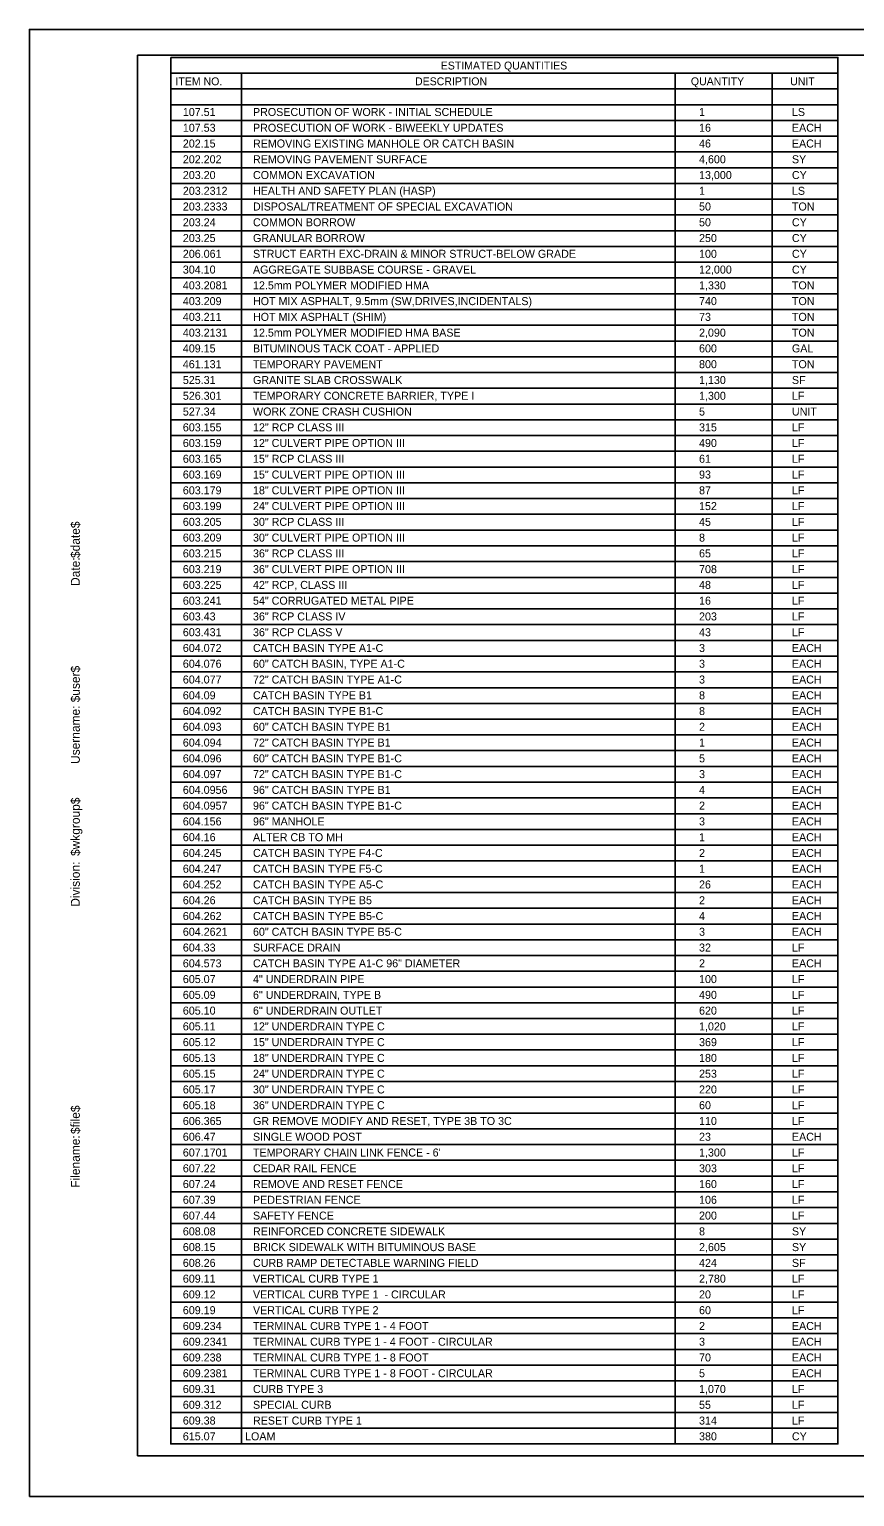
# Model space of a CAD drawing. Extents: x -0.13 to 2.7, y -0.05 to 1.78.
# Drawn here: x -0.135 to 0.896, y -0.051 to 1.782 of the extents above; entities that cross this region are included whole.
import ezdxf

# ---------------------------------------------------------------- set-up
doc = ezdxf.new("R2010")
doc.units = 0
for name, color, linetype in [('ANNOTATION', 7, 'Continuous'), ('BORDER', 7, 'Continuous'), ('PLOT BOUNDARY', 7, 'Continuous')]:
    doc.layers.add(name, color=color, linetype=linetype)

msp = doc.modelspace()

# ---------------------------------------------------------------- linework, layer by layer
at = {"layer": 'BORDER'}
for p, q in [((2.6667, 1.75), (0, 1.75)), ((0, 1.75), (0, 0)), ((0.0417, 1.7276), (0.875, 1.7276)), ((0.1302, 1.7276), (0.1302, 0.0149)), ((0.6716, 1.7276), (0.6716, 0.0149)), ((0.793, 1.7276), (0.793, 0.0149)), ((0.0417, 1.7079), (0.875, 1.7079)), ((0.0417, 1.6882), (0.875, 1.6882)), ((0.0417, 1.6685), (0.875, 1.6685)), ((0.0417, 1.6488), (0.875, 1.6488)), ((0.0417, 1.6292), (0.875, 1.6292)), ((0.0417, 1.6095), (0.875, 1.6095)), ((0.0417, 1.5898), (0.875, 1.5898)), ((0.0417, 1.5701), (0.875, 1.5701)), ((0.0417, 1.5504), (0.875, 1.5504)), ((0.0417, 1.5307), (0.875, 1.5307)), ((0.0417, 1.511), (0.875, 1.511)), ((0.0417, 1.4914), (0.875, 1.4914)), ((0.0417, 1.4717), (0.875, 1.4717)), ((0.0417, 1.452), (0.875, 1.452)), ((0.0417, 1.4323), (0.875, 1.4323)), ((0.0417, 1.4126), (0.875, 1.4126)), ((0.0417, 1.3929), (0.875, 1.3929)), ((0.0417, 1.3732), (0.875, 1.3732)), ((0.0417, 1.3536), (0.875, 1.3536)), ((0.0417, 1.3339), (0.875, 1.3339)), ((0.0417, 1.3142), (0.875, 1.3142)), ((0.0417, 1.2945), (0.875, 1.2945)), ((0.0417, 1.2748), (0.875, 1.2748)), ((0.0417, 1.2551), (0.875, 1.2551)), ((0.0417, 1.2354), (0.875, 1.2354)), ((0.0417, 1.2158), (0.875, 1.2158)), ((0.0417, 1.1961), (0.875, 1.1961)), ((0.0417, 1.1764), (0.875, 1.1764)), ((0.0417, 1.1567), (0.875, 1.1567)), ((0.0417, 1.137), (0.875, 1.137)), ((0.0417, 1.1173), (0.875, 1.1173)), ((0.0417, 1.0976), (0.875, 1.0976)), ((0.0417, 1.0779), (0.875, 1.0779)), ((0.0417, 1.0583), (0.875, 1.0583)), ((0.0417, 1.0386), (0.875, 1.0386)), ((0.0417, 1.0189), (0.875, 1.0189)), ((0.0417, 0.9992), (0.875, 0.9992)), ((0.0417, 0.9795), (0.875, 0.9795)), ((0.0417, 0.9598), (0.875, 0.9598)), ((0.0417, 0.9401), (0.875, 0.9401)), ((0.0417, 0.9205), (0.875, 0.9205)), ((0.0417, 0.9008), (0.875, 0.9008)), ((0.0417, 0.8811), (0.875, 0.8811)), ((0.0417, 0.8614), (0.875, 0.8614)), ((0.0417, 0.8417), (0.875, 0.8417)), ((0.0417, 0.822), (0.875, 0.822)), ((0.0417, 0.8023), (0.875, 0.8023)), ((0.0417, 0.7827), (0.875, 0.7827)), ((0.0417, 0.763), (0.875, 0.763)), ((0.0417, 0.7433), (0.875, 0.7433)), ((0.0417, 0.7236), (0.875, 0.7236)), ((0.0417, 0.7039), (0.875, 0.7039)), ((0.0417, 0.6842), (0.875, 0.6842)), ((0.0417, 0.6645), (0.875, 0.6645)), ((0.0417, 0.6449), (0.875, 0.6449)), ((0.0417, 0.6252), (0.875, 0.6252)), ((0.0417, 0.6055), (0.875, 0.6055)), ((0.0417, 0.5858), (0.875, 0.5858)), ((0.0417, 0.5661), (0.875, 0.5661)), ((0.0417, 0.5464), (0.875, 0.5464)), ((0.0417, 0.5267), (0.875, 0.5267)), ((0.0417, 0.5071), (0.875, 0.5071)), ((0.0417, 0.4874), (0.875, 0.4874)), ((0.0417, 0.4677), (0.875, 0.4677)), ((0.0417, 0.448), (0.875, 0.448)), ((0.0417, 0.4283), (0.875, 0.4283)), ((0.0417, 0.4086), (0.875, 0.4086)), ((0.0417, 0.3889), (0.875, 0.3889)), ((0.0417, 0.3693), (0.875, 0.3693)), ((0.0417, 0.3496), (0.875, 0.3496)), ((0.0417, 0.3299), (0.875, 0.3299)), ((0.0417, 0.3102), (0.875, 0.3102)), ((0.0417, 0.2905), (0.875, 0.2905)), ((0.0417, 0.2708), (0.875, 0.2708)), ((0.0417, 0.2511), (0.875, 0.2511)), ((0.0417, 0.2315), (0.875, 0.2315)), ((0.0417, 0.2118), (0.875, 0.2118)), ((0.0417, 0.1921), (0.875, 0.1921)), ((0.0417, 0.1724), (0.875, 0.1724)), ((0.0417, 0.1527), (0.875, 0.1527)), ((0.0417, 0.133), (0.875, 0.133)), ((0.0417, 0.1133), (0.875, 0.1133)), ((0.0417, 0.0936), (0.875, 0.0936)), ((0.0417, 0.074), (0.875, 0.074)), ((0.0417, 0.0543), (0.875, 0.0543)), ((0.0417, 0.0346), (0.875, 0.0346)), ((0, 0), (2.6667, 0)), ((0.0417, 0.0149), (0.875, 0.0149))]:
    msp.add_line(p, q, dxfattribs=at)
msp.add_lwpolyline([(0.0417, 1.7473), (0.875, 1.7473), (0.875, 0.0149), (0.0417, 0.0149)], close=True, dxfattribs=at)
at = {"layer": 'PLOT BOUNDARY'}
msp.add_lwpolyline([(-0.1349, -0.051), (2.6984, -0.051), (2.6984, 1.7823), (-0.1349, 1.7823)], close=True, dxfattribs=at)

# ---------------------------------------------------------------- texts
at = {"layer": 'ANNOTATION'}
for s, p in [('107.51', (0.0568, 1.6741)), ('PROSECUTION OF WORK - INITIAL SCHEDULE', (0.1444, 1.6741)), ('1', (0.7015, 1.6741)), ('LS', (0.8175, 1.6741)), ('107.53', (0.0568, 1.6544)), ('PROSECUTION OF WORK - BIWEEKLY UPDATES', (0.1444, 1.6544)), ('16', (0.7015, 1.6544)), ('EACH', (0.8175, 1.6544)), ('202.15', (0.0568, 1.6347)), ('REMOVING EXISTING MANHOLE OR CATCH BASIN', (0.1444, 1.6347)), ('46', (0.7015, 1.6347)), ('EACH', (0.8175, 1.6347)), ('202.202', (0.0568, 1.615)), ('REMOVING PAVEMENT SURFACE', (0.1444, 1.615)), ('4,600', (0.7015, 1.615)), ('SY', (0.8175, 1.615)), ('203.20', (0.0568, 1.5953)), ('COMMON EXCAVATION', (0.1444, 1.5953)), ('13,000', (0.7015, 1.5953)), ('CY', (0.8175, 1.5953)), ('203.2312', (0.0568, 1.5756)), ('HEALTH AND SAFETY PLAN (HASP)', (0.1444, 1.5756)), ('1', (0.7015, 1.5756)), ('LS', (0.8175, 1.5756)), ('203.2333', (0.0568, 1.556)), ('DISPOSAL/TREATMENT OF SPECIAL EXCAVATION', (0.1444, 1.556)), ('50', (0.7015, 1.556)), ('TON', (0.8175, 1.556)), ('203.24', (0.0568, 1.5363)), ('COMMON BORROW', (0.1444, 1.5363)), ('50', (0.7015, 1.5363)), ('CY', (0.8175, 1.5363)), ('203.25', (0.0568, 1.5166)), ('GRANULAR BORROW', (0.1444, 1.5166)), ('250', (0.7015, 1.5166)), ('CY', (0.8175, 1.5166)), ('206.061', (0.0568, 1.4969)), ('STRUCT EARTH EXC-DRAIN & MINOR STRUCT-BELOW GRADE', (0.1444, 1.4969)), ('100', (0.7015, 1.4969)), ('CY', (0.8175, 1.4969)), ('304.10', (0.0568, 1.4772)), ('AGGREGATE SUBBASE COURSE - GRAVEL', (0.1444, 1.4772)), ('12,000', (0.7015, 1.4772)), ('CY', (0.8175, 1.4772)), ('403.2081', (0.0568, 1.4575)), ('12.5mm POLYMER MODIFIED HMA', (0.1444, 1.4575)), ('1,330', (0.7015, 1.4575)), ('TON', (0.8175, 1.4575)), ('403.209', (0.0568, 1.4378)), ('HOT MIX ASPHALT, 9.5mm (SW,DRIVES,INCIDENTALS)', (0.1444, 1.4378)), ('740', (0.7015, 1.4378)), ('TON', (0.8175, 1.4378)), ('403.211', (0.0568, 1.4181)), ('HOT MIX ASPHALT (SHIM)', (0.1444, 1.4181)), ('73', (0.7015, 1.4181)), ('TON', (0.8175, 1.4181)), ('403.2131', (0.0568, 1.3984)), ('12.5mm POLYMER MODIFIED HMA BASE', (0.1444, 1.3984)), ('2,090', (0.7015, 1.3984)), ('TON', (0.8175, 1.3984)), ('409.15', (0.0568, 1.3787)), ('BITUMINOUS TACK COAT - APPLIED', (0.1444, 1.3787)), ('600', (0.7015, 1.3787)), ('GAL', (0.8175, 1.3787)), ('461.131', (0.0568, 1.359)), ('TEMPORARY PAVEMENT', (0.1444, 1.359)), ('800', (0.7015, 1.359)), ('TON', (0.8175, 1.359)), ('525.31', (0.0568, 1.3392)), ('GRANITE SLAB CROSSWALK', (0.1444, 1.3392)), ('1,130', (0.7015, 1.3392)), ('SF', (0.8175, 1.3392)), ('526.301', (0.0568, 1.3195)), ('TEMPORARY CONCRETE BARRIER, TYPE I', (0.1444, 1.3195)), ('1,300', (0.7015, 1.3195)), ('LF', (0.8175, 1.3195)), ('527.34', (0.0568, 1.2998)), ('WORK ZONE CRASH CUSHION', (0.1444, 1.2998)), ('5', (0.7015, 1.2998)), ('UNIT', (0.8175, 1.2998)), ('603.155', (0.0568, 1.2801)), ('12" RCP CLASS III', (0.1444, 1.2801)), ('315', (0.7015, 1.2801)), ('LF', (0.8175, 1.2801)), ('603.159', (0.0568, 1.2605)), ('12" CULVERT PIPE OPTION III', (0.1444, 1.2605)), ('490', (0.7015, 1.2605)), ('LF', (0.8175, 1.2605)), ('603.165', (0.0568, 1.2408)), ('15" RCP CLASS III', (0.1444, 1.2408)), ('61', (0.7015, 1.2408)), ('LF', (0.8175, 1.2408)), ('603.169', (0.0568, 1.2211)), ('15" CULVERT PIPE OPTION III', (0.1444, 1.2211)), ('93', (0.7015, 1.2211)), ('LF', (0.8175, 1.2211)), ('603.179', (0.0568, 1.2014)), ('18" CULVERT PIPE OPTION III', (0.1444, 1.2014)), ('87', (0.7015, 1.2014)), ('LF', (0.8175, 1.2014)), ('603.199', (0.0568, 1.1817)), ('24" CULVERT PIPE OPTION III', (0.1444, 1.1817)), ('152', (0.7015, 1.1817)), ('LF', (0.8175, 1.1817)), ('603.205', (0.0568, 1.162)), ('30" RCP CLASS III', (0.1444, 1.162)), ('45', (0.7015, 1.162)), ('LF', (0.8175, 1.162)), ('603.209', (0.0568, 1.1423)), ('30" CULVERT PIPE OPTION III', (0.1444, 1.1423)), ('8', (0.7015, 1.1423)), ('LF', (0.8175, 1.1423)), ('603.215', (0.0568, 1.1226)), ('36" RCP CLASS III', (0.1444, 1.1226)), ('65', (0.7015, 1.1226)), ('LF', (0.8175, 1.1226)), ('603.219', (0.0568, 1.1029)), ('36" CULVERT PIPE OPTION III', (0.1444, 1.1029)), ('708', (0.7015, 1.1029)), ('LF', (0.8175, 1.1029)), ('603.225', (0.0568, 1.0832)), ('42" RCP, CLASS III', (0.1444, 1.0832)), ('48', (0.7015, 1.0832)), ('LF', (0.8175, 1.0832)), ('603.241', (0.0568, 1.0635)), ('54" CORRUGATED METAL PIPE', (0.1444, 1.0635)), ('16', (0.7015, 1.0635)), ('LF', (0.8175, 1.0635)), ('603.43', (0.0568, 1.0438)), ('36" RCP CLASS IV', (0.1444, 1.0438)), ('203', (0.7015, 1.0438)), ('LF', (0.8175, 1.0438)), ('603.431', (0.0568, 1.0241)), ('36" RCP CLASS V', (0.1444, 1.0241)), ('43', (0.7015, 1.0241)), ('LF', (0.8175, 1.0241)), ('604.072', (0.0568, 1.0044)), ('CATCH BASIN TYPE A1-C', (0.1444, 1.0044)), ('3', (0.7015, 1.0044)), ('EACH', (0.8175, 1.0044)), ('604.076', (0.0568, 0.9847)), ('60" CATCH BASIN, TYPE A1-C', (0.1444, 0.9847)), ('3', (0.7015, 0.9847)), ('EACH', (0.8175, 0.9847)), ('604.077', (0.0568, 0.965)), ('72" CATCH BASIN TYPE A1-C', (0.1444, 0.965)), ('3', (0.7015, 0.965)), ('EACH', (0.8175, 0.965)), ('604.09', (0.0568, 0.9453)), ('CATCH BASIN TYPE B1', (0.1444, 0.9453)), ('8', (0.7015, 0.9453)), ('EACH', (0.8175, 0.9453)), ('604.092', (0.0568, 0.9256)), ('CATCH BASIN TYPE B1-C', (0.1444, 0.9256)), ('8', (0.7015, 0.9256)), ('EACH', (0.8175, 0.9256)), ('604.093', (0.0568, 0.9059)), ('60" CATCH BASIN TYPE B1', (0.1444, 0.9059)), ('2', (0.7015, 0.9059)), ('EACH', (0.8175, 0.9059)), ('604.094', (0.0568, 0.8862)), ('72" CATCH BASIN TYPE B1', (0.1444, 0.8862)), ('1', (0.7015, 0.8862)), ('EACH', (0.8175, 0.8862)), ('604.096', (0.0568, 0.8665)), ('60" CATCH BASIN TYPE B1-C', (0.1444, 0.8665)), ('5', (0.7015, 0.8665)), ('EACH', (0.8175, 0.8665)), ('604.097', (0.0568, 0.8468)), ('72" CATCH BASIN TYPE B1-C', (0.1444, 0.8468)), ('3', (0.7015, 0.8468)), ('EACH', (0.8175, 0.8468)), ('604.0956', (0.0568, 0.8271)), ('96" CATCH BASIN TYPE B1', (0.1444, 0.8271)), ('4', (0.7015, 0.8271)), ('EACH', (0.8175, 0.8271)), ('604.0957', (0.0568, 0.8074)), ('96" CATCH BASIN TYPE B1-C', (0.1444, 0.8074)), ('2', (0.7015, 0.8074)), ('EACH', (0.8175, 0.8074)), ('604.156', (0.0568, 0.7877)), ('96" MANHOLE', (0.1444, 0.7877)), ('3', (0.7015, 0.7877)), ('EACH', (0.8175, 0.7877)), ('604.16', (0.0568, 0.768)), ('ALTER CB TO MH', (0.1444, 0.768)), ('1', (0.7015, 0.768)), ('EACH', (0.8175, 0.768)), ('604.245', (0.0568, 0.7483)), ('CATCH BASIN TYPE F4-C', (0.1444, 0.7483)), ('2', (0.7015, 0.7483)), ('EACH', (0.8175, 0.7483)), ('604.247', (0.0568, 0.7286)), ('CATCH BASIN TYPE F5-C', (0.1444, 0.7286)), ('1', (0.7015, 0.7286)), ('EACH', (0.8175, 0.7286)), ('604.252', (0.0568, 0.7089)), ('CATCH BASIN TYPE A5-C', (0.1444, 0.7089)), ('26', (0.7015, 0.7089)), ('EACH', (0.8175, 0.7089)), ('604.26', (0.0568, 0.6892)), ('CATCH BASIN TYPE B5 ', (0.1444, 0.6892)), ('2', (0.7015, 0.6892)), ('EACH', (0.8175, 0.6892)), ('604.262', (0.0568, 0.6695)), ('CATCH BASIN TYPE B5-C', (0.1444, 0.6695)), ('4', (0.7015, 0.6695)), ('EACH', (0.8175, 0.6695)), ('604.2621', (0.0568, 0.6498)), ('60" CATCH BASIN TYPE B5-C', (0.1444, 0.6498)), ('3', (0.7015, 0.6498)), ('EACH', (0.8175, 0.6498)), ('604.33', (0.0568, 0.6301)), ('SURFACE DRAIN', (0.1444, 0.6301)), ('32', (0.7015, 0.6301)), ('LF', (0.8175, 0.6301)), ('604.573', (0.0568, 0.6104)), ('CATCH BASIN TYPE A1-C 96" DIAMETER', (0.1444, 0.6104)), ('2', (0.7015, 0.6104)), ('EACH', (0.8175, 0.6104)), ('605.07', (0.0568, 0.5907)), ('4" UNDERDRAIN PIPE', (0.1444, 0.5907)), ('100', (0.7015, 0.5907)), ('LF', (0.8175, 0.5907)), ('605.09', (0.0568, 0.571)), ('6" UNDERDRAIN, TYPE B', (0.1444, 0.571)), ('490', (0.7015, 0.571)), ('LF', (0.8175, 0.571)), ('605.10', (0.0568, 0.5513)), ('6" UNDERDRAIN OUTLET', (0.1444, 0.5513)), ('620', (0.7015, 0.5513)), ('LF', (0.8175, 0.5513)), ('605.11', (0.0568, 0.5316)), ('12" UNDERDRAIN TYPE C', (0.1444, 0.5316)), ('1,020', (0.7015, 0.5316)), ('LF', (0.8175, 0.5316)), ('605.12', (0.0568, 0.5119)), ('15" UNDERDRAIN TYPE C', (0.1444, 0.5119)), ('369', (0.7015, 0.5119)), ('LF', (0.8175, 0.5119)), ('605.13', (0.0568, 0.4922)), ('18" UNDERDRAIN TYPE C', (0.1444, 0.4922)), ('180', (0.7015, 0.4922)), ('LF', (0.8175, 0.4922)), ('605.15', (0.0568, 0.4725)), ('24" UNDERDRAIN TYPE C', (0.1444, 0.4725)), ('253', (0.7015, 0.4725)), ('LF', (0.8175, 0.4725)), ('605.17', (0.0568, 0.4528)), ('30" UNDERDRAIN TYPE C', (0.1444, 0.4528)), ('220', (0.7015, 0.4528)), ('LF', (0.8175, 0.4528)), ('605.18', (0.0568, 0.4331)), ('36" UNDERDRAIN TYPE C', (0.1444, 0.4331)), ('60', (0.7015, 0.4331)), ('LF', (0.8175, 0.4331)), ('606.365', (0.0568, 0.4134)), ('GR REMOVE MODIFY AND RESET, TYPE 3B TO 3C', (0.1444, 0.4134)), ('110', (0.7015, 0.4134)), ('LF', (0.8175, 0.4134)), ('606.47', (0.0568, 0.3937)), ('SINGLE WOOD POST', (0.1444, 0.3937)), ('23', (0.7015, 0.3937)), ('EACH', (0.8175, 0.3937)), ('607.1701', (0.0568, 0.374)), ("TEMPORARY CHAIN LINK FENCE - 6'", (0.1444, 0.374)), ('1,300', (0.7015, 0.374)), ('LF', (0.8175, 0.374)), ('607.22', (0.0568, 0.3543)), ('CEDAR RAIL FENCE', (0.1444, 0.3543)), ('303', (0.7015, 0.3543)), ('LF', (0.8175, 0.3543)), ('607.24', (0.0568, 0.3346)), ('REMOVE AND RESET FENCE', (0.1444, 0.3346)), ('160', (0.7015, 0.3346)), ('LF', (0.8175, 0.3346)), ('607.39', (0.0568, 0.3149)), ('PEDESTRIAN FENCE', (0.1444, 0.3149)), ('106', (0.7015, 0.3149)), ('LF', (0.8175, 0.3149)), ('607.44', (0.0568, 0.2952)), ('SAFETY FENCE', (0.1444, 0.2952)), ('200', (0.7015, 0.2952)), ('LF', (0.8175, 0.2952)), ('608.08', (0.0568, 0.2755)), ('REINFORCED CONCRETE SIDEWALK', (0.1444, 0.2755)), ('8', (0.7015, 0.2755)), ('SY', (0.8175, 0.2755)), ('608.15', (0.0568, 0.2558)), ('BRICK SIDEWALK WITH BITUMINOUS BASE', (0.1444, 0.2558)), ('2,605', (0.7015, 0.2558)), ('SY', (0.8175, 0.2558)), ('608.26', (0.0568, 0.2361)), ('CURB RAMP DETECTABLE WARNING FIELD', (0.1444, 0.2361)), ('424', (0.7015, 0.2361)), ('SF', (0.8175, 0.2361)), ('609.11', (0.0568, 0.2164)), ('VERTICAL CURB TYPE 1', (0.1444, 0.2164)), ('2,780', (0.7015, 0.2164)), ('LF', (0.8175, 0.2164)), ('609.12', (0.0568, 0.1967)), ('VERTICAL CURB TYPE 1  - CIRCULAR', (0.1444, 0.1967)), ('20', (0.7015, 0.1967)), ('LF', (0.8175, 0.1967)), ('609.19', (0.0568, 0.177)), ('VERTICAL CURB TYPE 2', (0.1444, 0.177)), ('60', (0.7015, 0.177)), ('LF', (0.8175, 0.177)), ('609.234', (0.0568, 0.1573)), ('TERMINAL CURB TYPE 1 - 4 FOOT', (0.1444, 0.1573)), ('2', (0.7015, 0.1573)), ('EACH', (0.8175, 0.1573)), ('609.2341', (0.0568, 0.1376)), ('TERMINAL CURB TYPE 1 - 4 FOOT - CIRCULAR', (0.1444, 0.1376)), ('3', (0.7015, 0.1376)), ('EACH', (0.8175, 0.1376)), ('609.238', (0.0568, 0.1179)), ('TERMINAL CURB TYPE 1 - 8 FOOT', (0.1444, 0.1179)), ('70', (0.7015, 0.1179)), ('EACH', (0.8175, 0.1179)), ('609.2381', (0.0568, 0.0982)), ('TERMINAL CURB TYPE 1 - 8 FOOT - CIRCULAR', (0.1444, 0.0982)), ('5', (0.7015, 0.0982)), ('EACH', (0.8175, 0.0982)), ('609.31', (0.0568, 0.0785)), ('CURB TYPE 3', (0.1444, 0.0785)), ('1,070', (0.7015, 0.0785)), ('LF', (0.8175, 0.0785)), ('609.312', (0.0568, 0.0588)), ('SPECIAL CURB', (0.1444, 0.0588)), ('55', (0.7015, 0.0588)), ('LF', (0.8175, 0.0588)), ('609.38', (0.0568, 0.0391)), ('RESET CURB TYPE 1', (0.1444, 0.0391)), ('314', (0.7015, 0.0391)), ('LF', (0.8175, 0.0391)), ('615.07', (0.0568, 0.0194)), ('LOAM', (0.1345, 0.0194)), ('380', (0.7015, 0.0194)), ('CY', (0.8175, 0.0194))]:
    msp.add_text(s, height=0.01, dxfattribs=at).set_placement(p)
at = {"layer": 'BORDER'}
for s, height, p in [('ESTIMATED QUANTITIES', 0.009843, (0.3789, 1.7322)), ('ITEM NO.', 0.00984, (0.0476, 1.7125)), ('DESCRIPTION', 0.009843, (0.3468, 1.7125)), ('QUANTITY', 0.00984, (0.6913, 1.7125)), ('UNIT', 0.00984, (0.8153, 1.7125))]:
    msp.add_text(s, height=height, dxfattribs=at).set_placement(p)
for s, p in [('$date$', (-0.0719, 1.1218)), ('Date:', (-0.0719, 1.0869)), ('$user$', (-0.0719, 0.9415)), ('Username:', (-0.0719, 0.8645)), ('$wkgroup$', (-0.0719, 0.7495)), ('Division:', (-0.0719, 0.6861)), ('$file$', (-0.0719, 0.4021)), ('Filename:', (-0.0719, 0.335))]:
    msp.add_text(s, height=0.01116, rotation=90, dxfattribs=at).set_placement(p)

doc.saveas('drawing.dxf')
